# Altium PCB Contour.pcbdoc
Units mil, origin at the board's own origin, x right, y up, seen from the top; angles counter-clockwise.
Board outline 4330.8 x 4330.8 mil, 2 copper layers (Top Layer, Bottom Layer), stack 62.2 mil thick; 34 components, 17 nets, 106 pads, 9 vias.
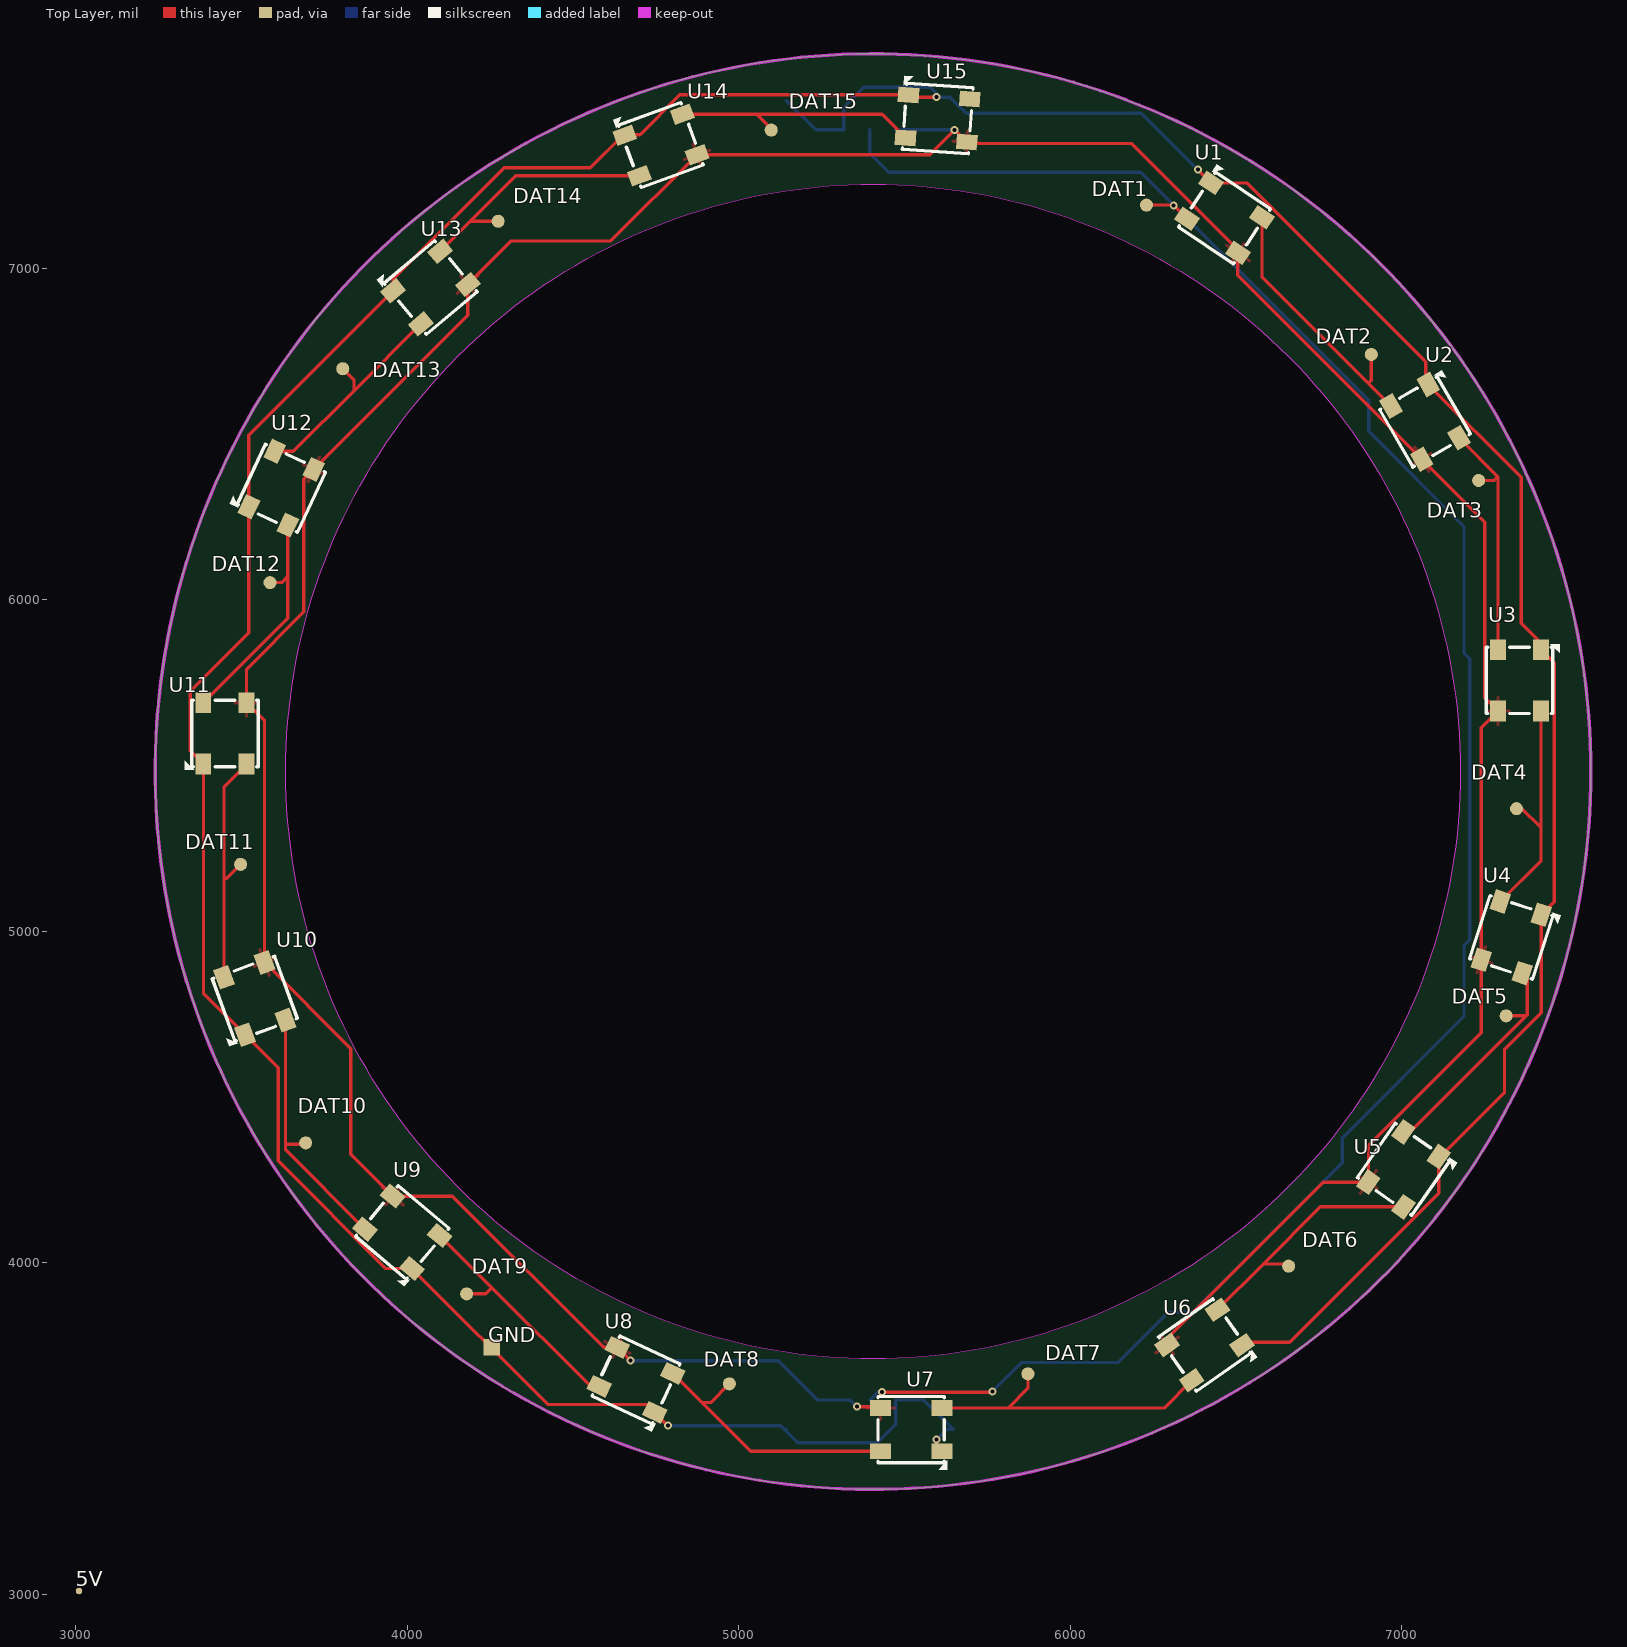
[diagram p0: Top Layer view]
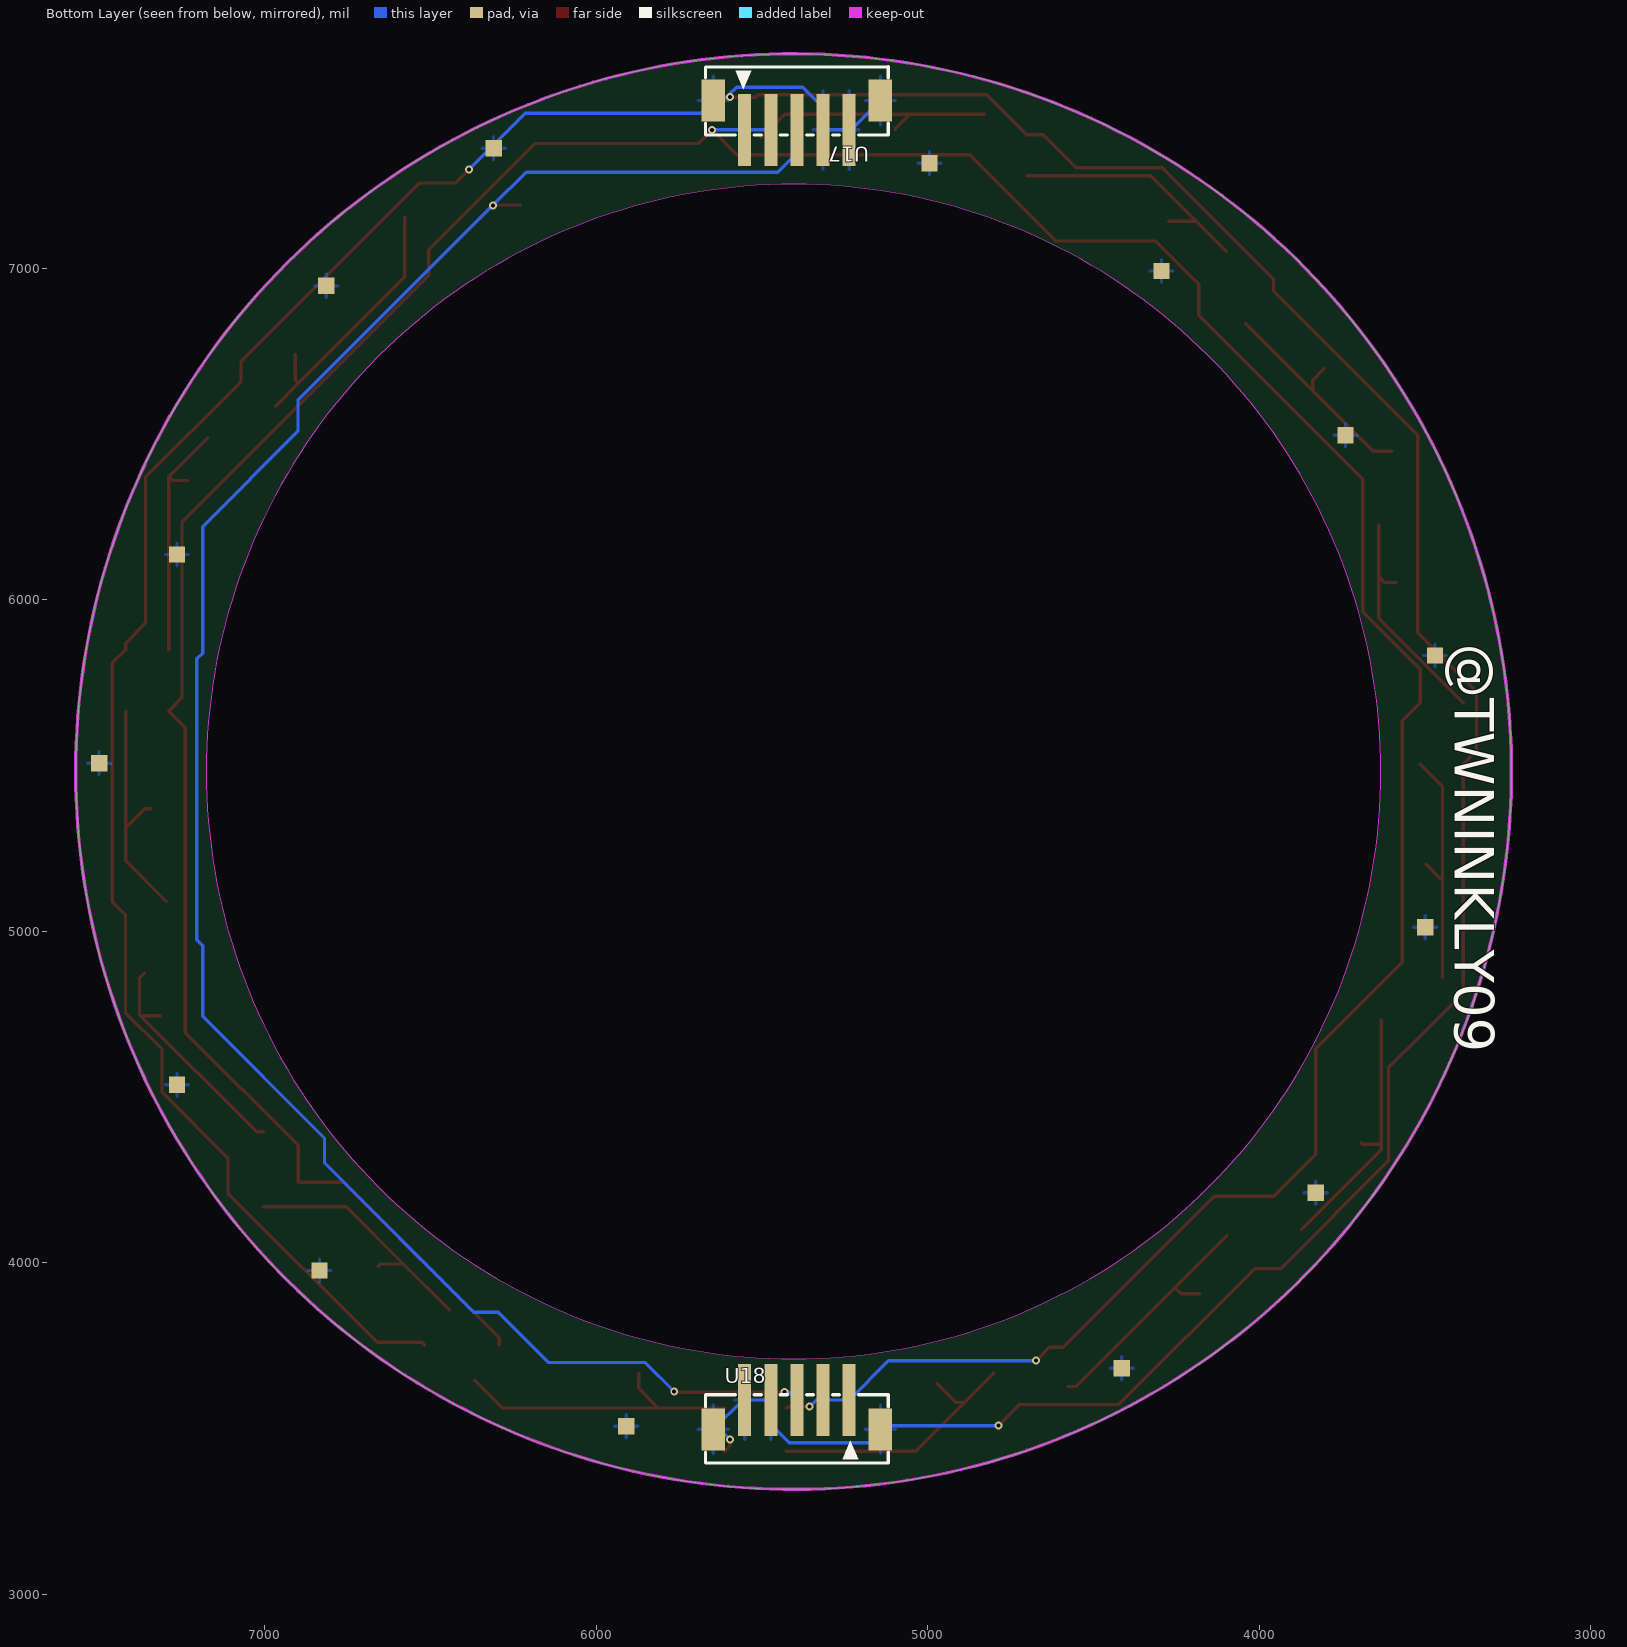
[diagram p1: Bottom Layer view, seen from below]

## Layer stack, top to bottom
Top Solder Mask Layer: solder mask 0.4, Dk 3.3
Top Layer: signal copper 1.4
Dielectric1: surface 59.4, FR4, Dk 4.5
Bottom Layer: signal copper 1.4
Bottom Solder Mask Layer: solder mask 0.4, Dk 3.3

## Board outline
7570.5,5481.6 ccw(c5405.1,5481.6) 3239.7,5481.6 ccw(c5405.1,5481.6)
cut-out: 7176.8,5481.6 7176.4,5444 7175.2,5406.4 7173.2,5368.9 7170.4,5331.4 7166.8,5294 7162.4,5256.6 7157.2,5219.4 7151.3,5182.2 7144.5,5145.2 7137,5108.4 7128.7,5071.7 7119.6,5035.2 7109.7,4998.9 7099.1,4962.9 7087.7,4927 7075.6,4891.4 7062.6,4856.1 7049,4821.1 7034.6,4786.3 7019.5,4751.9 7003.6,4717.8 6987.1,4684 6969.8,4650.6 6951.8,4617.6 6933.1,4585 6913.7,4552.7 6893.7,4520.9 6872.9,4489.6 6851.5,4458.6 6829.5,4428.2 6806.8,4398.2 6783.5,4368.6 6759.6,4339.6 6735,4311.1 6709.9,4283.2 6684.2,4255.8 6657.8,4228.9 6631,4202.6 6603.6,4176.8 6575.6,4151.7 6547.1,4127.2 6518.1,4103.2 6488.6,4079.9 6458.6,4057.2 6428.1,4035.2 6397.2,4013.8 6365.8,3993.1 6334,3973 6301.8,3953.6 6269.1,3935 6236.1,3917 6202.7,3899.7 6168.9,3883.1 6134.8,3867.3 6100.4,3852.1 6065.7,3837.7 6030.6,3824.1 5995.3,3811.2 5959.7,3799 5923.9,3787.6 5887.8,3777 5851.5,3767.1 5815,3758.1 5778.4,3749.7 5741.5,3742.2 5704.5,3735.5 5667.4,3729.5 5630.1,3724.3 5592.8,3720 5555.3,3716.4 5517.8,3713.6 5480.3,3711.6 5442.7,3710.4 5405.1,3710 5367.5,3710.4 5329.9,3711.6 5292.4,3713.6 5254.9,3716.4 5217.4,3720 5180.1,3724.3 5142.8,3729.5 5105.7,3735.5 5068.7,3742.2 5031.8,3749.7 4995.2,3758.1 4958.7,3767.1 4922.4,3777 4886.3,3787.6 4850.5,3799 4814.9,3811.2 4779.6,3824.1 4744.5,3837.7 4709.8,3852.1 4675.4,3867.3 4641.3,3883.1 4607.5,3899.7 4574.1,3917 4541.1,3935 4508.4,3953.6 4476.2,3973 4444.4,3993.1 4413,4013.8 4382.1,4035.2 4351.6,4057.2 4321.6,4079.9 4292.1,4103.2 4263.1,4127.2 4234.6,4151.7 4206.6,4176.8 4179.2,4202.6 4152.4,4228.9 4126,4255.8 4100.3,4283.2 4075.2,4311.1 4050.6,4339.6 4026.7,4368.6 4003.4,4398.2 3980.7,4428.2 3958.7,4458.6 3937.3,4489.6 3916.5,4520.9 3896.5,4552.7 3877.1,4585 3858.4,4617.6 3840.4,4650.6 3823.1,4684 3806.6,4717.8 3790.7,4751.9 3775.6,4786.3 3761.2,4821.1 3747.6,4856.1 3734.6,4891.4 3722.5,4927 3711.1,4962.9 3700.5,4998.9 3690.6,5035.2 3681.5,5071.7 3673.2,5108.4 3665.7,5145.2 3658.9,5182.2 3653,5219.4 3647.8,5256.6 3643.4,5294 3639.8,5331.4 3637,5368.9 3635,5406.4 3633.8,5444 3633.4,5481.6 3633.8,5519.2 3635,5556.8 3637,5594.4 3639.8,5631.9 3643.4,5669.3 3647.8,5706.7 3653,5743.9 3658.9,5781 3665.7,5818 3673.2,5854.9 3681.5,5891.6 3690.6,5928.1 3700.5,5964.3 3711.1,6000.4 3722.5,6036.3 3734.6,6071.8 3747.6,6107.2 3761.2,6142.2 3775.6,6177 3790.7,6211.4 3806.6,6245.5 3823.1,6279.2 3840.4,6312.6 3858.4,6345.7 3877.1,6378.3 3896.5,6410.5 3916.5,6442.3 3937.3,6473.7 3958.7,6504.6 3980.7,6535.1 4003.4,6565.1 4026.7,6594.6 4050.6,6623.6 4075.2,6652.1 4100.3,6680.1 4126,6707.5 4152.4,6734.4 4179.2,6760.7 4206.6,6786.4 4234.6,6811.6 4263.1,6836.1 4292.1,6860 4321.6,6883.4 4351.6,6906 4382.1,6928.1 4413,6949.5 4444.4,6970.2 4476.2,6990.2 4508.4,7009.6 4541.1,7028.3 4574.1,7046.3 4607.5,7063.6 4641.3,7080.2 4675.4,7096 4709.8,7111.1 4744.5,7125.5 4779.6,7139.2 4814.9,7152.1 4850.5,7164.2 4886.3,7175.6 4922.4,7186.3 4958.7,7196.1 4995.2,7205.2 5031.8,7213.5 5068.7,7221.1 5105.7,7227.8 5142.8,7233.8 5180.1,7238.9 5217.4,7243.3 5254.9,7246.9 5292.4,7249.7 5329.9,7251.7 5367.5,7252.9 5405.1,7253.3 5442.7,7252.9 5480.3,7251.7 5517.8,7249.7 5555.3,7246.9 5592.8,7243.3 5630.1,7238.9 5667.4,7233.8 5704.5,7227.8 5741.5,7221.1 5778.4,7213.5 5815,7205.2 5851.5,7196.1 5887.8,7186.3 5923.9,7175.6 5959.7,7164.2 5995.3,7152.1 6030.6,7139.2 6065.7,7125.5 6100.4,7111.1 6134.8,7096 6168.9,7080.2 6202.7,7063.6 6236.1,7046.3 6269.1,7028.3 6301.8,7009.6 6334,6990.2 6365.8,6970.2 6397.2,6949.5 6428.1,6928.1 6458.6,6906 6488.6,6883.4 6518.1,6860 6547.1,6836.1 6575.6,6811.6 6603.6,6786.4 6631,6760.7 6657.8,6734.4 6684.2,6707.5 6709.9,6680.1 6735,6652.1 6759.6,6623.6 6783.5,6594.6 6806.8,6565.1 6829.5,6535.1 6851.5,6504.6 6872.9,6473.7 6893.7,6442.3 6913.7,6410.5 6933.1,6378.3 6951.8,6345.7 6969.8,6312.6 6987.1,6279.2 7003.6,6245.5 7019.5,6211.4 7034.6,6177 7049,6142.2 7062.6,6107.2 7075.6,6071.8 7087.7,6036.3 7099.1,6000.4 7109.7,5964.3 7119.6,5928.1 7128.7,5891.6 7137,5854.9 7144.5,5818 7151.3,5781 7157.2,5743.9 7162.4,5706.7 7166.8,5669.3 7170.4,5631.9 7173.2,5594.4 7175.2,5556.8 7176.4,5519.2

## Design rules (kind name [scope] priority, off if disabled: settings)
BoardOutlineClearance copperThickness1oz [All] p0: genericclearance=10 ignorepadtopadclearanceinfootprint=FALSE except(0: Arc-SplitContinuation Track-SplitContinuation SMDPad-SplitContinuation THPad-SplitContinuation Via-SplitContinuation Fill-SplitContinuation Poly-SplitContinuation Region-SplitContinuation Text-SplitContinuation)
BoardOutlineClearance copperThickness2oz [All] p0: genericclearance=10 ignorepadtopadclearanceinfootprint=FALSE except(0: Arc-SplitContinuation Track-SplitContinuation SMDPad-SplitContinuation THPad-SplitContinuation Via-SplitContinuation Fill-SplitContinuation Poly-SplitContinuation Region-SplitContinuation Text-SplitContinuation)
BoardOutlineClearance Plane_innerPlane [All] p0: genericclearance=10 ignorepadtopadclearanceinfootprint=FALSE except(0: Arc-SplitContinuation Track-SplitContinuation SMDPad-SplitContinuation THPad-SplitContinuation Via-SplitContinuation Fill-SplitContinuation Poly-SplitContinuation Region-SplitContinuation Text-SplitContinuation)
BoardOutlineClearance Copper_copperRegion [All] p0: genericclearance=10 ignorepadtopadclearanceinfootprint=FALSE except(0: Arc-SplitContinuation Track-SplitContinuation SMDPad-SplitContinuation THPad-SplitContinuation Via-SplitContinuation Fill-SplitContinuation Poly-SplitContinuation Region-SplitContinuation Text-SplitContinuation)
BoardOutlineClearance otherClearance [All] p0: genericclearance=10 ignorepadtopadclearanceinfootprint=FALSE except(0: Arc-SplitContinuation Track-SplitContinuation SMDPad-SplitContinuation THPad-SplitContinuation Via-SplitContinuation Fill-SplitContinuation Poly-SplitContinuation Region-SplitContinuation Text-SplitContinuation)
Clearance copperThickness1oz [All] p1: gap=7 ignorepadtopadclearanceinfootprint=FALSE
Clearance copperThickness2oz [All] p1: gap=7 ignorepadtopadclearanceinfootprint=FALSE
Clearance Plane_innerPlane [All] p1: gap=7 ignorepadtopadclearanceinfootprint=FALSE
Clearance Copper_copperRegion [All] p1: gap=7 ignorepadtopadclearanceinfootprint=FALSE
Clearance otherClearance [All] p1: gap=7 ignorepadtopadclearanceinfootprint=FALSE
DiffPairsRouting differentialPair [All] p1: maxuncoupledlength=10 minlimit=6 maxlimit=Infinity mostfreqgap=6 toplayer_minwidth=5 toplayer_prefwidth=10 toplayer_maxwidth=100 bottomlayer_minwidth=5 bottomlayer_prefwidth=10 bottomlayer_maxwidth=100
PasteMaskExpansion pasteMaskExpansion [All] p1: expansion=0
PlaneConnect innerPlane [All] p1: planeconnectstyle=Relief reliefexpansion=20 reliefentries=4 reliefconductorwidth=10 reliefairgap=10
PolygonConnect copperRegion [All] p1: connectstyle=Relief reliefentries=4 reliefconductorwidth=10 polygonreliefangle="90 Angle" airgapwidth=10
RoutingVias viaSize [All] p1: viastyle="Through Hole" holewidth=12.0078 minholewidth=11.811 maxholewidth=248.0314 width=12.0078 minwidth=11.811 maxwidth=248.0314
SolderMaskExpansion solderMaskExpansion [IsVia] p1: useseparateexpansions=TRUE expansion=-1000 expansionbottom=-1000
SolderMaskExpansion solderMaskExpansion [All] p2: useseparateexpansions=TRUE expansion=2 expansionbottom=2
Width copperThickness1oz [All] p1: maxlimit=100 minlimit=5 preferedwidth=10
Width copperThickness2oz [All] p1: maxlimit=100 minlimit=8 preferedwidth=10

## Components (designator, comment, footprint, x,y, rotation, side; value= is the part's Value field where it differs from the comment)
5V "" Test-Point-0.5mm#1 3009.8,3009.8 r0 top
DAT1 "" Test-Point-0.5mm#2 6229.8,7190.5 r0 top
DAT2 "" Test-Point-0.5mm#2 6908,6739.8 r0 top
DAT3 "" Test-Point-0.5mm#2 7231.7,6359.8 r0 top
DAT4 "" Test-Point-0.5mm#2 7346.1,5369.8 r0 top
DAT5 "" Test-Point-0.5mm#2 7314.8,4744.8 r0 top
DAT6 "" Test-Point-0.5mm#2 6658.5,3989.8 r0 top
DAT7 "" Test-Point-0.5mm#2 5872.3,3664.8 r0 top
DAT8 "" Test-Point-0.5mm#2 4971.7,3634.8 r0 top
DAT9 "" Test-Point-0.5mm#2 4179.2,3906.1 r0 top
DAT10 "" Test-Point-0.5mm#2 3693.6,4361.7 r0 top
DAT11 "" Test-Point-0.5mm#2 3497.3,5201.7 r0 top
DAT12 "" Test-Point-0.5mm#2 3586.1,6051.7 r0 top
DAT13 "" Test-Point-0.5mm#2 3805.4,6696.7 r0 top
DAT14 "" Test-Point-0.5mm#2 4274.2,7141.7 r0 top
DAT15 "" Test-Point-0.5mm#2 5097.9,7416.7 r0 top
GND "" Test-Point-0.5mm#3 4254.8,3745.5 r0 top
U1 "SK6812" LED-SMD_4P-L5.0-W5.0-LS5.4-TL-1#1 6465.1,7151.6 r146 top
U2 "SK6812" LED-SMD_4P-L5.0-W5.0-LS5.4-TL-1#2 7070.1,6536.6 r120 top
U3 "SK6812" LED-SMD_4P-L5.0-W5.0-LS5.4-TL-1#3 7355.1,5756.6 r90 top
U4 "SK6812" LED-SMD_4P-L5.0-W5.0-LS5.4-TL-1#4 7330.1,4981.6 r72 top
U5 "SK6812" LED-SMD_4P-L5.0-W5.0-LS5.4-TL-1#5 7005.1,4281.6 r55 top
U6 "SK6812" LED-SMD_4P-L5.0-W5.0-LS5.4-TL-1#4 6405.1,3751.6 r35 top
U7 "SK6812" LED-SMD_4P-L5.0-W5.0-LS5.4-TL-1#6 5520.1,3496.6 r0 top
U8 "SK6812" LED-SMD_4P-L5.0-W5.0-LS5.4-TL-1#6 4690.1,3646.6 r335 top
U9 "SK6812" LED-SMD_4P-L5.0-W5.0-LS5.4-TL-1#7 3985.1,4091.6 r320 top
U10 "SK6812" LED-SMD_4P-L5.0-W5.0-LS5.4-TL-1#8 3540.1,4796.6 r290 top
U11 "SK6812" LED-SMD_4P-L5.0-W5.0-LS5.4-TL-1#9 3450.1,5596.6 r270 top
U12 "SK6812" LED-SMD_4P-L5.0-W5.0-LS5.4-TL-1#7 3620.1,6336.6 r245 top
U13 "SK6812" LED-SMD_4P-L5.0-W5.0-LS5.4-TL-1#10 4070.1,6941.6 r220 top
U14 "SK6812" LED-SMD_4P-L5.0-W5.0-LS5.4-TL-1#4 4765.1,7371.6 r200 top
U15 "SK6812" LED-SMD_4P-L5.0-W5.0-LS5.4-TL-1#11 5600.1,7451.6 r176 top
U17 "B5B-PH-SM4-TB(LF)(SN)" CONN-SMD_5P-P2.00_B6B-PH-SM4-TB-LF-SN 5395.1,7461.6 r0 bottom
U18 "B5B-PH-SM4-TB(LF)(SN)" CONN-SMD_5P-P2.00_B6B-PH-SM4-TB-LF-SN 5395.1,3541.6 r180 bottom

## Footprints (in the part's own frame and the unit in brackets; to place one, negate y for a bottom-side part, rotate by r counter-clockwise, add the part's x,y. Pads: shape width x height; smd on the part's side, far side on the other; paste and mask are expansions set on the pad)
CONN-SMD_5P-P2.00_B6B-PH-SM4-TB-LF-SN [mil]
  rect 39.4x216.5 smd: 1(157.5,44.3) 2(78.7,44.3) 3(0,44.3) 4(-78.7,44.3) 5(-157.5,44.3)
  rect 70.9x126 smd: 6(252,-44.3) 7(-252,-44.3)
  silkscreen extent -276,-146 276,60
LED-SMD_4P-L5.0-W5.0-LS5.4-TL-1#1 [mil]
  rect 63x47.2 smd paste+0 mask+2: 1(-92.54,64.95) 2(-92.45,-65.01) 3(92.54,-64.95) 4(92.51,64.93)
  silkscreen extent -100,-122 109,100
LED-SMD_4P-L5.0-W5.0-LS5.4-TL-1#2 [mil]
  rect 63x47.2 smd paste+0 mask+2: 1(-92.51,64.96) 2(-92.47,-64.97) 3(92.51,-64.96) 4(92.56,64.92)
  silkscreen extent -100,-122 109,100
LED-SMD_4P-L5.0-W5.0-LS5.4-TL-1#3 [mil]
  rect 63x47.2 smd paste+0 mask+2: 1(-92.5,65) 2(-92.5,-65) 3(92.6,-65) 4(92.6,65)
  silkscreen extent -100,-122 109,100
LED-SMD_4P-L5.0-W5.0-LS5.4-TL-1#4 [mil]
  rect 63x47.2 smd paste+0 mask+2: 1(-92.51,64.99) 2(-92.45,-64.95) 3(92.61,-64.96) 4(92.55,64.98)
  silkscreen extent -100,-121 109,100
LED-SMD_4P-L5.0-W5.0-LS5.4-TL-1#5 [mil]
  rect 63x47.2 smd paste+0 mask+2: 1(-92.51,64.99) 2(-92.51,-64.9) 3(92.59,-64.94) 4(92.59,64.95)
  silkscreen extent -100,-122 109,100
LED-SMD_4P-L5.0-W5.0-LS5.4-TL-1#6 [mil]
  rect 63x47.2 smd paste+0 mask+2: 1(-92.5,65) 2(-92.5,-64.9) 3(92.5,-64.9) 4(92.5,65)
  silkscreen extent -100,-121 109,100
LED-SMD_4P-L5.0-W5.0-LS5.4-TL-1#7 [mil]
  rect 63x47.2 smd paste+0 mask+2: 1(-92.55,65.02) 2(-92.49,-64.95) 3(92.48,-64.95) 4(92.49,64.95)
  silkscreen extent -100,-121 109,100
LED-SMD_4P-L5.0-W5.0-LS5.4-TL-1#8 [mil]
  rect 63x47.2 smd paste+0 mask+2: 1(-92.56,64.98) 2(-92.6,-64.95) 3(92.47,-64.94) 4(92.5,64.98)
  silkscreen extent -100,-121 109,100
LED-SMD_4P-L5.0-W5.0-LS5.4-TL-1#9 [mil]
  rect 63x47.2 smd paste+0 mask+2: 1(-92.6,65) 2(-92.6,-65) 3(92.5,-65) 4(92.5,65)
  silkscreen extent -100,-121 109,100
LED-SMD_4P-L5.0-W5.0-LS5.4-TL-1#10 [mil]
  rect 63x47.2 smd paste+0 mask+2: 1(-92.49,64.95) 2(-92.55,-65.02) 3(92.49,-64.95) 4(92.48,64.95)
  silkscreen extent -100,-122 109,100
LED-SMD_4P-L5.0-W5.0-LS5.4-TL-1#11 [mil]
  rect 63x47.2 smd paste+0 mask+2: 1(-92.55,64.9) 2(-92.49,-65.01) 3(92.56,-65) 4(92.5,64.91)
  silkscreen extent -100,-122 109,100
Test-Point-0.5mm#1 [mil]
  round 19.7 smd: 1(0,0)
Test-Point-0.5mm#2 [mil]
  round 39.4 smd: 1(0,0)
Test-Point-0.5mm#3 [mil]
  rect 49.4x49.4 smd: 1(0,0)

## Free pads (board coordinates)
  rect 49.4x49.4 smd far side: 1(3470.1,5831.6) 1(3500.1,5011.6) 1(3740.1,6496.6) 1(3830.1,4211.6) 1(4295.1,6991.6) 1(4415.1,3681.6) 1(4995.1,7316.6) 1(5910.1,3506.6) 1(6310.1,7361.6) 1(6815.1,6946.6) 1(6835.1,3976.6) 1(7265.1,4536.6) 1(7265.1,6136.6) 1(7500.1,5506.6)
  round 24 hole 12: 1(5765.1,3611.6)

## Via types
v1: diameter 24, hole 12, Top Layer to Bottom Layer, 9 vias

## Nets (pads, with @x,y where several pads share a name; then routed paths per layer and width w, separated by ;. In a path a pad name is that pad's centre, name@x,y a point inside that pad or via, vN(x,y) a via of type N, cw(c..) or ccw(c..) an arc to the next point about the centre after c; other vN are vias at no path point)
5V: 5V.1 U1.1 U2.1 U3.1 U4.1 U5.1 U6.1 U7.1 U8.1 U9.1 U10.1 U11.1 U12.1 U13.1 U14.1 U15.1 U17.1 U17.2 U18.1 U18.2 | length 11910.4
  Top Layer w10: v1(4673.7,3704.6) U8.1 4592.2,3744.6 4136,4200.9 U9.1 3829.5,4327.4 3829.5,4645.8 U10.1 3569.5,5634.7 U11.1 3515.1,5790 3688.1,5963 3688.1,6363 U12.1 4182.7,6857.7 U13.1 4313.6,7082.2 4614.3,7082.2 U14.1 5575.8,7342.2 v1(5650.9,7417.3) U15.1 5692.2,7376 6185.5,7376 6505.5,7056 U1.1 6505.5,6978.7 U2.1 7250.1,6234 7250.1,5704.2 U3.1 7239.7,5613.7 U4.1 7239.7,4693.7 6899.7,4353.7 6899.7,4244 U5.1 6763.4,4243.1 6293.4,3773.1 6293.4,3753.1 U6.1 ; v1(5356.4,3565.9) 5423.3,3565.9 U7.1
  Bottom Layer w10: v1(4673.7,3704.6) 5118.9,3704.6 U18.1 U18.2 5336.4,3585.9 v1(5356.4,3565.9) ; U17.2 U17.1 v1(5650.9,7417.3)
$1N1276: DAT3.1 U2.2 U3.4 | length 751.7
  Top Layer w10: U2.2 7290.1,6371.5 ; DAT3.1 7278.5,6359.8 7290.1,6371.5 ; U3.4 7290.1,6371.5
$1N1280: DAT2.1 U1.2 U2.4 | length 821.7
  Top Layer w10: U1.2 6578.1,6973.7 6899.1,6652.7 ; DAT2.1 6908,6661.5 6899.1,6652.7 ; U2.4 6899.1,6652.7
$1N1284: DAT10.1 U9.2 U10.4 | length 792.5
  Top Layer w10: U10.4 3632.8,4357.3 ; DAT10.1 3689.1,4357.3 3632.8,4357.3 ; U9.2 3632.8,4341 3632.8,4357.3
$1N1308: DAT11.1 U10.2 U11.4 | length 738
  Top Layer w10: U10.2 3447.4,5159.8 ; DAT11.1 3455.4,5159.8 3447.4,5159.8 ; U11.4 3447.4,5436.5 3447.4,5159.8
$1N1314: DAT12.1 U11.2 U12.4 | length 703.3
  Top Layer w10: U11.2 3639.9,5943.9 3639.9,6070.5 ; DAT12.1 3621.1,6051.7 3639.9,6070.5 ; U12.4 3639.9,6070.5
$1N1319: DAT5.1 U4.2 U5.4 | length 711.8
  Top Layer w10: U5.4 7025,4394.7 7378.3,4748 7378.3,4858.6 U4.2 ; DAT5.1 7375.1,4744.8
$1N1323: DAT13.1 U12.2 U13.4 | length 679.9
  Top Layer w10: U12.2 3656.5,6447.9 3839.4,6630.8 ; DAT13.1 3839.4,6662.7 3839.4,6630.8 ; U13.4 3839.4,6630.8
$1N1327: DAT6.1 U5.2 U6.4 | length 769.6
  Top Layer w10: U6.4 6581.8,3996.1 ; DAT6.1 6652.3,3996.1 6581.8,3996.1 ; U5.2 6754.3,4168.6 6581.8,3996.1
$1N1331: DAT7.1 U6.2 U7.4 | length 916.6
  Top Layer w10: U7.4 5812.6,3561.6 ; DAT7.1 5872.3,3621.3 5812.6,3561.6 ; U6.2 6282.8,3561.6 5812.6,3561.6
$1N1335: DAT8.1 U7.2 U8.4 | length 828.9
  Top Layer w10: U8.4 4889.6,3578.3 ; DAT8.1 4915.1,3578.3 4889.6,3578.3 ; U7.2 5036.1,3431.7 4889.6,3578.3
$1N1339: DAT15.1 U14.2 U15.4 | length 768.4
  Top Layer w10: U14.2 5054.7,7464.3 ; DAT15.1 5097.9,7421.2 5054.7,7464.3 ; U15.4 5432.2,7464.3 5054.7,7464.3
$1N1343: DAT14.1 U13.2 U14.4 | length 779.7
  Top Layer w10: U13.2 4190.1,7141.7 ; DAT14.1 4190.1,7141.7 ; U14.4 4327.3,7278.9 4190.1,7141.7
$1N1347: DAT4.1 U3.2 U4.4 | length 723.5
  Top Layer w10: U4.4 7420.1,5212.9 7420.1,5311.7 ; DAT4.1 7361.9,5369.8 7420.1,5311.7 ; U3.2 7420.1,5311.7
$1N1943: DAT9.1 U8.2 U9.4 | length 753
  Top Layer w10: U9.4 4254.9,3924.8 ; DAT9.1 4236.2,3906.1 4254.9,3924.8 ; U8.2 4552.8,3626.9 4254.9,3924.8
DIN: DAT1.1 pad.1@5765.1,3611.6 U1.4 U17.3 U18.3 | length 6330.3
  Top Layer w10: v1(5432.1,3609.5) 5763,3609.5 pad.1@5765.1,3611.6 ; DAT1.1 6311.1,7190.5 v1(6312.1,7189.5) U1.4
  Bottom Layer w10: U18.3 5418.7,3609.5 v1(5432.1,3609.5) ; U17.3 5395.1,7347.3 5452.9,7289.5 6212.1,7289.5 v1(6312.1,7189.5) 6900.1,6601.5 6900.1,6507.7 7187.7,6220 7187.7,5839 7205.1,5821.6 7205.1,4974 7187.7,4956.6 7187.7,4743.2 6820.1,4375.6 6820.1,4301.6 6369.6,3851.1 6295.6,3851.1 6143.5,3699 5852.5,3699 pad.1@5765.1,3611.6
GND: GND.1 pad.1@3470.1,5831.6 pad.1@3500.1,5011.6 pad.1@3740.1,6496.6 pad.1@3830.1,4211.6 pad.1@4295.1,6991.6 pad.1@4415.1,3681.6 pad.1@4995.1,7316.6 pad.1@5910.1,3506.6 pad.1@6310.1,7361.6 pad.1@6815.1,6946.6 pad.1@6835.1,3976.6 pad.1@7265.1,4536.6 pad.1@7265.1,6136.6 pad.1@7500.1,5506.6 U1.3 U2.3 U3.3 U4.3 U5.3 U6.3 U7.3 U8.3 U9.3 U10.3 U11.3 U12.3 U13.3 U14.3 U15.3 U17.4 U17.5 U17.6 U17.7 U18.4 U18.5 U18.6 U18.7 | length 13534.9
  Top Layer w10: U14.3 U14.3@4652.3,7402.9 ; v1(4786.5,3508.7) U8.3 4722.8,3572.4 4424.2,3572.4 U9.3 3935.8,3982.4 3610.7,4307.5 3610.7,4587.5 U10.3 3385.1,4813 U11.3 3345.1,5544.1 3345.1,5723.3 3522.1,5900.2 U12.3 3522.1,6496.6 U13.3 3957.5,6968 4292.3,7302.9 4552.3,7302.9 U14.3@4652.3,7402.9 ; v1(5597.1,3467.3) 5597.1,3447.2 U7.3 ; v1(5597.1,7515.9) 5519.3,7515.9 U15.3 4822.3,7522.9 4702.3,7402.9 U14.3@4652.3,7402.9 ; v1(6384.7,7297.2) U1.3 6532.1,7257.2 7072.1,6717.2 7072.1,6657.2 U2.3 7360.1,6369.2 7360.1,5929.2 7420.1,5869.3 U3.3@7420.1,5849.3 ; U6.3 6526.8,3760.2 6661.4,3760.2 7111.4,4210.2 7111.4,4315.2 7310.1,4513.9 7310.1,4644.2 7420.5,4754.6 U4.3 7460.1,5089.1 7460.1,5809.3 U3.3@7420.1,5849.3 ; U3.3 U3.3@7420.1,5849.3
  Bottom Layer w10: v1(4786.5,3508.7) 5126.5,3508.7 U18.6@5137.8,3497.3 ; U18.6 U18.6@5137.8,3497.3 ; U17.7 5231.7,7417.3 U17.5 U17.4 5316.4,7485.2 5377.1,7545.9 5577.1,7545.9 5597.1,7525.9 v1(5597.1,7515.9) 5637.1,7515.9 U17.6 5685.8,7467.2 6214.7,7467.2 v1(6384.7,7297.2) ; v1(5597.1,3467.3) 5627.1,3497.3 U18.7 5558.5,3585.9 U18.5 U18.4 5473.8,3513.4 5417.8,3457.3 5177.8,3457.3 U18.6@5137.8,3497.3
pads on no net: U15.2

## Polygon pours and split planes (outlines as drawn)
5V on Top Layer (solid, remove dead copper, pour order 0): 3000.1,7666.6 3000.1,3216.6 7570.1,3216.6 7570.1,7666.6
GND on Bottom Layer (solid, remove dead copper, pour order 2): 3140.1,7726.6 3140.1,3256.6 7940.1,3256.6 7940.1,7726.6

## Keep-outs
Board Outline Layer:
  region: 297 vertices and 0 holes, not listed, extent 3633.4,3710 7176.8,7253.3
  region: 297 vertices and 0 holes, not listed, extent 3633.4,3710 7176.8,7253.3
  lines w0.1: 3633.4,5481.6 3633.8,5444 3635,5406.4 3637,5368.9 3639.8,5331.4 3643.4,5294 3647.8,5256.6 3653,5219.4 3658.9,5182.2 3665.7,5145.2 3673.2,5108.4 3681.5,5071.7 3690.6,5035.2 3700.5,4998.9 3711.1,4962.9 3722.5,4927 3734.6,4891.4 3747.6,4856.1 3761.2,4821.1 3775.6,4786.3 3790.7,4751.9 3806.6,4717.8 3823.1,4684 3840.4,4650.6 3858.4,4617.6 3877.1,4585 3896.5,4552.7 3916.5,4520.9 3937.3,4489.6 3958.7,4458.6 3980.7,4428.2 4003.4,4398.2 4026.7,4368.6 4050.6,4339.6 4075.2,4311.1 4100.3,4283.2 4126,4255.8 4152.4,4228.9 4179.2,4202.6 4206.6,4176.8 4234.6,4151.7 4263.1,4127.2 4292.1,4103.2 4321.6,4079.9 4351.6,4057.2 4382.1,4035.2 4413,4013.8 4444.4,3993.1 4476.2,3973 4508.4,3953.6 4541.1,3935 4574.1,3917 4607.5,3899.7 4641.3,3883.1 4675.4,3867.3 4709.8,3852.1 4744.5,3837.7 4779.6,3824.1 4814.9,3811.2 4850.5,3799 4886.3,3787.6 4922.4,3777 4958.7,3767.1 4995.2,3758.1 5031.8,3749.7 5068.7,3742.2 5105.7,3735.5 5142.8,3729.5 5180.1,3724.3 5217.4,3720 5254.9,3716.4 5292.4,3713.6 5329.9,3711.6 5367.5,3710.4 5405.1,3710 5442.7,3710.4 5480.3,3711.6 5517.8,3713.6 5555.3,3716.4 5592.8,3720 5630.1,3724.3 5667.4,3729.5 5704.5,3735.5 5741.5,3742.2 5778.4,3749.7 5815,3758.1 5851.5,3767.1 5887.8,3777 5923.9,3787.6 5959.7,3799 5995.3,3811.2 6030.6,3824.1 6065.7,3837.7 6100.4,3852.1 6134.8,3867.3 6168.9,3883.1 6202.7,3899.7 6236.1,3917 6269.1,3935 6301.8,3953.6 6334,3973 6365.8,3993.1 6397.2,4013.8 6428.1,4035.2 6458.6,4057.2 6488.6,4079.9 6518.1,4103.2 6547.1,4127.2 6575.6,4151.7 6603.6,4176.8 6631,4202.6 6657.8,4228.9 6684.2,4255.8 6709.9,4283.2 6735,4311.1 6759.6,4339.6 6783.5,4368.6 6806.8,4398.2 6829.5,4428.2 6851.5,4458.6 6872.9,4489.6 6893.7,4520.9 6913.7,4552.7 6933.1,4585 6951.8,4617.6 6969.8,4650.6 6987.1,4684 7003.6,4717.8 7019.5,4751.9 7034.6,4786.3 7049,4821.1 7062.6,4856.1 7075.6,4891.4 7087.7,4927 7099.1,4962.9 7109.7,4998.9 7119.6,5035.2 7128.7,5071.7 7137,5108.4 7144.5,5145.2 7151.3,5182.2 7157.2,5219.4 7162.4,5256.6 7166.8,5294 7170.4,5331.4 7173.2,5368.9 7175.2,5406.4 7176.4,5444 7176.8,5481.6 7176.4,5519.2 7175.2,5556.8 7173.2,5594.4 7170.4,5631.9 7166.8,5669.3 7162.4,5706.7 7157.2,5743.9 7151.3,5781 7144.5,5818 7137,5854.9 7128.7,5891.6 7119.6,5928.1 7109.7,5964.3 7099.1,6000.4 7087.7,6036.3 7075.6,6071.8 7062.6,6107.2 7049,6142.2 7034.6,6177 7019.5,6211.4 7003.6,6245.5 6987.1,6279.2 6969.8,6312.6 6951.8,6345.7 6933.1,6378.3 6913.7,6410.5 6893.7,6442.3 6872.9,6473.7 6851.5,6504.6 6829.5,6535.1 6806.8,6565.1 6783.5,6594.6 6759.6,6623.6 6735,6652.1 6709.9,6680.1 6684.2,6707.5 6657.8,6734.4 6631,6760.7 6603.6,6786.4 6575.6,6811.6 6547.1,6836.1 6518.1,6860 6488.6,6883.4 6458.6,6906 6428.1,6928.1 6397.2,6949.5 6365.8,6970.2 6334,6990.2 6301.8,7009.6 6269.1,7028.3 6236.1,7046.3 6202.7,7063.6 6168.9,7080.2 6134.8,7096 6100.4,7111.1 6065.7,7125.5 6030.6,7139.2 5995.3,7152.1 5959.7,7164.2 5923.9,7175.6 5887.8,7186.3 5851.5,7196.1 5815,7205.2 5778.4,7213.5 5741.5,7221.1 5704.5,7227.8 5667.4,7233.8 5630.1,7238.9 5592.8,7243.3 5555.3,7246.9 5517.8,7249.7 5480.3,7251.7 5442.7,7252.9 5405.1,7253.3 5367.5,7252.9 5329.9,7251.7 5292.4,7249.7 5254.9,7246.9 5217.4,7243.3 5180.1,7238.9 5142.8,7233.8 5105.7,7227.8 5068.7,7221.1 5031.8,7213.5 4995.2,7205.2 4958.7,7196.1 4922.4,7186.3 4886.3,7175.6 4850.5,7164.2 4814.9,7152.1 4779.6,7139.2 4744.5,7125.5 4709.8,7111.1 4675.4,7096 4641.3,7080.2 4607.5,7063.6 4574.1,7046.3 4541.1,7028.3 4508.4,7009.6 4476.2,6990.2 4444.4,6970.2 4413,6949.5 4382.1,6928.1 4351.6,6906 4321.6,6883.4 4292.1,6860 4263.1,6836.1 4234.6,6811.6 4206.6,6786.4 4179.2,6760.7 4152.4,6734.4 4126,6707.5 4100.3,6680.1 4075.2,6652.1 4050.6,6623.6 4026.7,6594.6 4003.4,6565.1 3980.7,6535.1 3958.7,6504.6 3937.3,6473.7 3916.5,6442.3 3896.5,6410.5 3877.1,6378.3 3858.4,6345.7 3840.4,6312.6 3823.1,6279.2 3806.6,6245.5 3790.7,6211.4 3775.6,6177 3761.2,6142.2 3747.6,6107.2 3734.6,6071.8 3722.5,6036.3 3711.1,6000.4 3700.5,5964.3 3690.6,5928.1 3681.5,5891.6 3673.2,5854.9 3665.7,5818 3658.9,5781 3653,5743.9 3647.8,5706.7 3643.4,5669.3 3639.8,5631.9 3637,5594.4 3635,5556.8 3633.8,5519.2 3633.4,5481.6
  lines w10: 3239.8,5460.8 3240.6,5419.2 3242.2,5377.7 3244.6,5336.1 3247.8,5294.6 3251.8,5253.2 3256.6,5211.9 3262.2,5170.7 3268.6,5129.6 3275.7,5088.6 3283.7,5047.7 3292.4,5007 3301.9,4966.5 3312.2,4926.2 3323.2,4886.1 3335.1,4846.2 3347.7,4806.6 3361,4767.2 3375.1,4728 3390,4689.2 3405.6,4650.6 3421.9,4612.3 3439,4574.4 3456.8,4536.8 3475.3,4499.5 3494.5,4462.6 3514.4,4426.1 3535.1,4390 3556.4,4354.2 3578.4,4318.9 3601.1,4284 3624.4,4249.6 3648.4,4215.6 3673.1,4182.1 3698.4,4149.1 3724.3,4116.5 3750.8,4084.5 3778,4052.9 3805.7,4021.9 3834,3991.5 3863,3961.6 3892.5,3932.2 3922.5,3903.4 3953.1,3875.3 3984.2,3847.6 4015.9,3820.7 4048.1,3794.3 4080.7,3768.5 4113.9,3743.4 4147.5,3718.9 4181.6,3695.1 4216.2,3671.9 4251.2,3649.4 4286.6,3627.5 4322.4,3606.4 4358.7,3585.9 4395.3,3566.2 4432.3,3547.1 4469.6,3528.8 4507.3,3511.2 4545.3,3494.3 4583.7,3478.1 4622.3,3462.7 4661.2,3448.1 4700.5,3434.1 4739.9,3421 4779.6,3408.6 4819.6,3396.9 4859.8,3386.1 4900.1,3376 4940.7,3366.7 4981.4,3358.1 5022.3,3350.4 5063.3,3343.4 5104.4,3337.3 5145.7,3331.9 5187,3327.3 5228.5,3323.5 5270,3320.5 5311.5,3318.3 5353.1,3316.9 5394.7,3316.3 5436.3,3316.5 5477.9,3317.5 5519.5,3319.3 5561,3321.9 5602.5,3325.3 5643.9,3329.5 5685.2,3334.5 5726.4,3340.2 5767.4,3346.8 5808.4,3354.2 5849.2,3362.3 5889.8,3371.2 5930.3,3380.9 5970.6,3391.4 6010.6,3402.7 6050.4,3414.7 6090,3427.5 6129.4,3441 6168.5,3455.3 6207.2,3470.3 6245.7,3486.1 6283.9,3502.6 6321.8,3519.9 6359.3,3537.9 6396.5,3556.6 6433.3,3576 6469.7,3596.1 6505.7,3616.9 6541.4,3638.4 6576.6,3660.5 6611.3,3683.4 6645.7,3706.9 6679.5,3731.1 6712.9,3755.9 6745.9,3781.3 6778.3,3807.4 6810.2,3834.1 6841.6,3861.4 6872.5,3889.3 6902.8,3917.8 6932.6,3946.8 6961.8,3976.5 6990.4,4006.6 7018.4,4037.4 7045.9,4068.6 7072.7,4100.4 7099,4132.7 7124.6,4165.5 7149.5,4198.8 7173.9,4232.5 7197.5,4266.8 7220.6,4301.4 7242.9,4336.5 7264.6,4372 7285.5,4408 7305.8,4444.3 7325.4,4481 7344.3,4518.1 7362.4,4555.5 7379.9,4593.3 7396.6,4631.4 7412.5,4669.8 7427.7,4708.6 7442.2,4747.6 7456,4786.8 7468.9,4826.4 7481.1,4866.1 7492.6,4906.1 7503.3,4946.4 7513.1,4986.8 7522.3,5027.4 7530.6,5068.1 7538.2,5109 7544.9,5150.1 7550.9,5191.3 7556.1,5232.5 7560.5,5273.9 7564.1,5315.4 7566.9,5356.9 7568.9,5398.4 7570.1,5440 7570.5,5481.6 7570.1,5523.2 7568.9,5564.8 7566.9,5606.4 7564.1,5647.9 7560.5,5689.3 7556.1,5730.7 7550.9,5772 7544.9,5813.2 7538.2,5854.2 7530.6,5895.1 7522.3,5935.9 7513.1,5976.5 7503.3,6016.9 7492.6,6057.1 7481.1,6097.1 7468.9,6136.9 7456,6176.4 7442.2,6215.7 7427.7,6254.7 7412.5,6293.4 7396.6,6331.9 7379.9,6370 7362.4,6407.7 7344.3,6445.2 7325.4,6482.3 7305.8,6519 7285.5,6555.3 7264.6,6591.2 7242.9,6626.7 7220.6,6661.8 7197.5,6696.5 7173.9,6730.7 7149.5,6764.5 7124.6,6797.8 7099,6830.5 7072.7,6862.8 7045.9,6894.6 7018.4,6925.9 6990.4,6956.6 6961.8,6986.8 6932.6,7016.4 6902.8,7045.5 6872.5,7074 6841.6,7101.9 6810.2,7129.2 6778.3,7155.9 6745.9,7182 6712.9,7207.4 6679.5,7232.2 6645.7,7256.4 6611.3,7279.9 6576.6,7302.7 6541.4,7324.9 6505.7,7346.4 6469.7,7367.2 6433.3,7387.3 6396.5,7406.7 6359.3,7425.4 6321.8,7443.4 6283.9,7460.6 6245.7,7477.1 6207.2,7492.9 6168.5,7508 6129.4,7522.3 6090,7535.8 6050.4,7548.6 6010.6,7560.6 5970.6,7571.9 5930.3,7582.3 5889.8,7592 5849.2,7601 5808.4,7609.1 5767.4,7616.5 5726.4,7623 5685.2,7628.8 5643.9,7633.8 5602.5,7638 5561,7641.4 5519.5,7644 5477.9,7645.8 5436.3,7646.8 5394.7,7647 5353.1,7646.4 5311.5,7645 5270,7642.8 5228.5,7639.8 5187,7636 5145.7,7631.4 5104.4,7626 5063.3,7619.8 5022.3,7612.9 4981.4,7605.1 4940.7,7596.6 4900.1,7587.3 4859.8,7577.2 4819.6,7566.3 4779.6,7554.7 4739.9,7542.3 4700.5,7529.1 4661.2,7515.2 4622.3,7500.5 4583.7,7485.1 4545.3,7469 4507.3,7452.1 4469.6,7434.5 4432.3,7416.1 4395.3,7397.1 4358.7,7377.3 4322.4,7356.9 4286.6,7335.7 4251.2,7313.9 4216.2,7291.4 4181.6,7268.2 4147.5,7244.4 4113.9,7219.9 4080.7,7194.8 4048.1,7169 4015.9,7142.6 3984.2,7115.6 3953.1,7088 3922.5,7059.8 3892.5,7031 3863,7001.7 3834,6971.8 3805.7,6941.3 3778,6910.3 3750.8,6878.8 3724.3,6846.8 3698.4,6814.2 3673.1,6781.2 3648.4,6747.7 3624.4,6713.7 3601.1,6679.2 3578.4,6644.3 3556.4,6609 3535.1,6573.3 3514.4,6537.2 3494.5,6500.7 3475.3,6463.8 3456.8,6426.5 3439,6388.9 3421.9,6350.9 3405.6,6312.7 3390,6274.1 3375.1,6235.2 3361,6196.1 3347.7,6156.7 3335.1,6117 3323.2,6077.2 3312.2,6037 3301.9,5996.7 3292.4,5956.2 3283.7,5915.5 3275.7,5874.7 3268.6,5833.7 3262.2,5792.6 3256.6,5751.4 3251.8,5710 3247.8,5668.6 3244.6,5627.1 3242.2,5585.6 3240.6,5544 3239.8,5502.4 3239.8,5460.8

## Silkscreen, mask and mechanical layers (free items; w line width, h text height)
Bottom Silkscreen Layer:
  text "@TWNINKLY09" at 3410.1,5866.6 h120 r90
Mechanical Layer:
  drawing of 296 lines, arcs and shapes, not listed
